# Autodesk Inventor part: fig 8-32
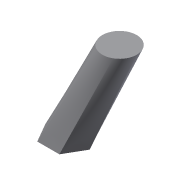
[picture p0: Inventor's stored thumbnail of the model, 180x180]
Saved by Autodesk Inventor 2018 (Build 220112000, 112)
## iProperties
Shininess: 77.0
Angle Display Precision: 2
Document Length Units: 11269
Document Angle Units: 11279
Document Time Units: 11290
Document Mass Units: 11283
Document Length Units Precision: 3
Document Angle Units Precision: 2
Created: 2001-12
Part Number: fig 8-32
Document SubType Name: Modeling
Designer: CADSoft
Density: 1 g/cm^3
Material: Generic
Appearance: Default
Density: 0.0
Volumn: 0.0
Area: 0.0
PropertySet Name: Model Information
Control State: 0
Master: False
Checked Out: False
Author: CADSoft
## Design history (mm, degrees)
workplane "Work Plane3"
workplane "Work Plane4"
sketch "Sketch12"
  geometry: L1 (0, 10.598)-(9.178, -5.299); L2 (9.178, -5.299)-(-9.178, -5.299); L3 (-9.178, -5.299)-(0, 10.598); 1 further point
  constraints: 6 end point, 5 other
workplane "Work Plane5"
workplane "Work Plane6"
workplane "Work Plane7"
sketch "Sketch16"
  geometry: A1 r 72.799 centre (23.007, 110.594) between (0, 41.527) and (70, 54.995); 1 further point
  constraints: 2 point on circle, 1 centre point
loft "Loft5" dims "d57" = 0, "d58" = 90 deg, "d59" = 0, "d60" = 90 deg
body "Solid2"
sketch "Sketch1"
  geometry: L1 (19.387, 0)-(9.693, -16.79); L2 (9.693, -16.79)-(-9.693, -16.79); L3 (-9.693, -16.79)-(-19.387, 0); L4 (-19.387, 0)-(-9.693, 16.79); L5 (-9.693, 16.79)-(9.693, 16.79); L6 (9.693, 16.79)-(19.387, 0); 1 further point
  constraints: 12 end point, 11 other
sketch "Sketch2"
  geometry: C1 r 15 at (23.06, 22.535)
  constraints: 1 centre point
